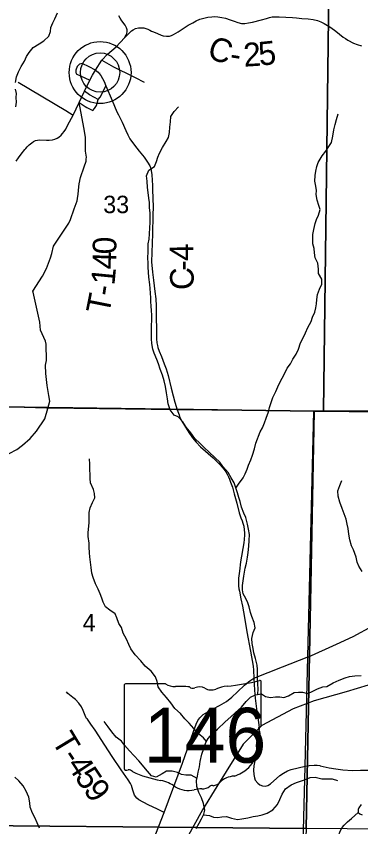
# Model space of a CAD drawing. Extents: x 0 to 191, y 0 to 55.
# Drawn here: x 144.645 to 145.059, y 20.34 to 21.314 of the extents above; entities that cross this region are included whole.
import ezdxf

# ---------------------------------------------------------------- set-up
doc = ezdxf.new("R2010")
doc.units = 0
for name, color, linetype in [('GM_X_Corporation', 7, 'Continuous'), ('GM_X_County_Road', 7, 'Continuous'), ('GM_X_County_Road_Text', 7, 'Continuous'), ('GM_X_Minor_River', 7, 'Continuous'), ('GM_X_Rail_Line', 7, 'Continuous'), ('GM_X_Section_Text', 7, 'Continuous'), ('GM_X_State_Location', 7, 'Continuous'), ('GM_X_State_Route', 7, 'Continuous'), ('GM_X_State_Shield', 7, 'Continuous'), ('GM_X_Township_Road', 7, 'Continuous'), ('GM_X_Township_Road_Text', 7, 'Continuous'), ('GM_X_Unincorporated', 7, 'Continuous'), ('GM_X_Unincorporated_Location', 7, 'Continuous')]:
    doc.layers.add(name, color=color, linetype=linetype)

msp = doc.modelspace()

# ---------------------------------------------------------------- linework, layer by layer
at = {"layer": 'GM_X_Corporation'}
for points in [[(145.17243, 20.8379), (145.0026, 20.83935), (144.83879, 20.8412), (144.83813, 20.84121), (144.68247, 20.843), (144.68103, 20.84301), (144.48078, 20.84928), (144.48001, 20.8493), (144.38601, 20.85042), (144.38393, 20.85044), (143.76753, 20.85776), (143.76581, 20.85778), (143.59684, 20.85979), (143.59377, 20.85978), (143.43969, 20.86008), (143.44633, 20.9725), (143.44634, 20.97335), (143.45423, 21.44428), (143.46697, 22.05758), (143.46706, 22.06228), (143.47318, 22.50936)], [(144.98772, 20.24394), (144.99193, 20.41256), (144.99195, 20.41315), (144.99523, 20.54421), (144.99523, 20.54446), (145.0026, 20.83935), (144.83879, 20.8412), (144.83813, 20.84121), (144.68247, 20.843), (144.68103, 20.84301), (144.48078, 20.84928), (144.48001, 20.8493), (144.38601, 20.85042), (144.38393, 20.85044), (143.76753, 20.85776), (143.76581, 20.85778), (143.59684, 20.85979), (143.59377, 20.85978), (143.43969, 20.86008), (143.27549, 20.86338), (143.27549, 18.61761)], [(144.98772, 20.24394), (144.99193, 20.41256), (144.99195, 20.41315), (144.99523, 20.54421), (144.99523, 20.54446), (145.0026, 20.83935), (145.17243, 20.8379)]]:
    msp.add_lwpolyline(points, dxfattribs=at)
for points in [[(144.51719, 21.34898), (145.0205, 21.34372), (145.01412, 20.83983), (145.00275, 20.8397), (144.50909, 20.84639)], [(145.51832, 21.3384), (145.5104, 20.8362), (145.49144, 20.83655), (145.01412, 20.83983), (145.0205, 21.34372)], [(144.46967, 20.84688), (144.50909, 20.84639), (145.00275, 20.8397), (144.99311, 20.33823), (144.46404, 20.34281)], [(145.00275, 20.8397), (145.01412, 20.83983), (145.49144, 20.83655), (145.48618, 20.33399), (144.99311, 20.33823)], [(144.99311, 20.33823), (144.97358, 19.84025), (144.45738, 19.84668), (144.46404, 20.34281)]]:
    msp.add_lwpolyline(points, close=True, dxfattribs=at)
at = {"layer": 'GM_X_County_Road'}
for points in [[(144.77467, 21.28794), (144.78151, 21.29498), (144.78314, 21.29631), (144.78544, 21.29775), (144.78821, 21.29905), (144.79148, 21.29994), (144.79433, 21.30016), (144.79813, 21.29985), (144.80067, 21.29919), (144.80275, 21.29833), (144.80513, 21.29728), (144.80738, 21.29617), (144.80973, 21.29512), (144.81433, 21.29312), (144.81901, 21.29102), (144.82136, 21.29024), (144.82518, 21.28983), (144.82915, 21.29008), (144.83133, 21.29058), (144.83377, 21.29185), (144.8392, 21.29526), (144.84646, 21.29994), (144.85158, 21.30323), (144.8569, 21.30614), (144.86119, 21.30855), (144.86557, 21.31021), (144.87019, 21.31162), (144.87512, 21.31273), (144.8798, 21.31326), (144.88318, 21.31342), (144.8872, 21.31315), (144.89204, 21.31248), (144.89639, 21.31151), (144.90174, 21.30977), (144.90667, 21.30797), (144.91132, 21.30642), (144.91545, 21.30531), (144.91952, 21.30525), (144.92387, 21.30584), (144.92896, 21.30689), (144.93979, 21.30946), (144.94544, 21.31126), (144.9491, 21.31234), (144.95228, 21.31312), (144.95516, 21.31331), (144.96095, 21.31301), (144.97701, 21.3124), (144.98172, 21.31187), (144.98812, 21.31126), (144.99579, 21.31077), (145.00158, 21.31007), (145.00693, 21.30866), (145.01094, 21.30717), (145.01476, 21.3052), (145.02285, 21.30041), (145.02911, 21.29603), (145.03786, 21.28897), (145.04049, 21.287), (145.04337, 21.28506), (145.05035, 21.28152), (145.05456, 21.27986), (145.05991, 21.2785)], [(144.73977, 21.24925), (144.74297, 21.24687), (144.74453, 21.24513), (144.74635, 21.24271), (144.74843, 21.23915), (144.75025, 21.23559), (144.75243, 21.23033), (144.75988, 21.21252), (144.76569, 21.19908), (144.76768, 21.19535), (144.77189, 21.18663), (144.77627, 21.17649), (144.77874, 21.17133), (144.78126, 21.16664), (144.78681, 21.1591), (144.79262, 21.15177), (144.7983, 21.14448), (144.80264, 21.13859), (144.80533, 21.13416), (144.80663, 21.13095), (144.8071, 21.12844), (144.80771, 21.12323), (144.8084, 21.11075), (144.80862, 21.10533), (144.80918, 21.08494), (144.8091, 21.07493), (144.8085, 21.05261), (144.80723, 21.0189), (144.80832, 21.00637), (144.80953, 20.99696), (144.8114, 20.98321), (144.81239, 20.97436), (144.81287, 20.96621), (144.81291, 20.95814), (144.81296, 20.95069), (144.81313, 20.93924), (144.81322, 20.92631), (144.81369, 20.92163), (144.81452, 20.91834), (144.81504, 20.91595), (144.81651, 20.91148), (144.8192, 20.90511), (144.82267, 20.89648), (144.82488, 20.89032), (144.8274, 20.8823), (144.83099, 20.86721), (144.83317, 20.8581), (144.8352, 20.85034), (144.83823, 20.84094), (144.84045, 20.83492)], [(144.84045, 20.83492), (144.84113, 20.83307), (144.84149, 20.83208), (144.8437, 20.82749), (144.84808, 20.8202), (144.85212, 20.81391), (144.85676, 20.80728), (144.86101, 20.80207), (144.86621, 20.79678), (144.8813, 20.78325), (144.88954, 20.77549), (144.89245, 20.77211), (144.8944, 20.76968), (144.89657, 20.7666), (144.89826, 20.76387), (144.89995, 20.76079), (144.90121, 20.75793), (144.90251, 20.75437), (144.90454, 20.74804), (144.9068, 20.74011), (144.90975, 20.72905), (144.91291, 20.71725), (144.91487, 20.7114), (144.91634, 20.70758), (144.91721, 20.70489), (144.9182, 20.70121), (144.9189, 20.69683), (144.91911, 20.69349), (144.91911, 20.69106), (144.91868, 20.68529), (144.91825, 20.68143), (144.91452, 20.65845), (144.91296, 20.64739), (144.912, 20.63894), (144.91183, 20.63408), (144.91205, 20.62953), (144.91248, 20.62597), (144.91296, 20.62328), (144.91478, 20.61413), (144.91664, 20.60515), (144.91898, 20.59167), (144.92193, 20.57441), (144.92627, 20.55116), (144.92948, 20.53313), (144.92996, 20.52822), (144.93021, 20.51878)], [(144.93021, 20.51878), (144.93128, 20.50436), (144.93209, 20.49471), (144.93339, 20.482), (144.93587, 20.46546), (144.93659, 20.45931), (144.93654, 20.45445), (144.93602, 20.45001), (144.9354, 20.44257), (144.93447, 20.43435), (144.93235, 20.42329), (144.93054, 20.41358), (144.93003, 20.4082), (144.93018, 20.40319), (144.93101, 20.39901), (144.93209, 20.39606), (144.93509, 20.3927), (144.93773, 20.39069), (144.94078, 20.38945), (144.94439, 20.38903), (144.94724, 20.38996), (144.95034, 20.39177), (144.96156, 20.40191), (144.96596, 20.40474), (144.9707, 20.40743), (144.9754, 20.40903), (144.99205, 20.41288), (144.99685, 20.41379), (145.00294, 20.41415), (145.00672, 20.41425), (145.00984, 20.41371)], [(145.00984, 20.41371), (145.01028, 20.41363), (145.02113, 20.41125), (145.02904, 20.4097), (145.03757, 20.40846), (145.04888, 20.408), (145.05875, 20.40826), (145.07162, 20.40826)], [(145.05927, 20.36707), (145.05674, 20.36319), (145.05591, 20.36102), (145.05565, 20.35911), (145.05581, 20.35735), (145.05793, 20.3556), (145.06082, 20.35456)]]:
    msp.add_lwpolyline(points, dxfattribs=at)
at = {"layer": 'GM_X_Minor_River'}
for points in [[(144.64376, 21.23443), (144.64501, 21.24108), (144.64741, 21.24699), (144.65057, 21.25347), (144.65448, 21.25995), (144.65707, 21.26548), (144.66005, 21.27025), (144.66491, 21.27656), (144.67225, 21.28062), (144.6779, 21.28428), (144.68389, 21.29003), (144.68592, 21.29555), (144.68644, 21.30048), (144.68847, 21.30581), (144.69088, 21.31096), (144.6944, 21.3182)], [(144.64424, 21.20505), (144.64476, 21.21055), (144.6447, 21.21624), (144.64484, 21.22117), (144.64384, 21.22647)], [(144.80425, 21.12914), (144.81102, 21.13357), (144.81342, 21.13928), (144.81507, 21.14461), (144.81711, 21.14956), (144.82064, 21.15604), (144.82511, 21.16329), (144.82771, 21.16844), (144.82897, 21.17433), (144.82928, 21.18078), (144.82998, 21.18724), (144.83067, 21.19331), (144.83458, 21.19942), (144.83983, 21.20497)], [(144.90886, 20.7472), (144.91187, 20.75172), (144.91747, 20.75956), (144.92007, 20.76432), (144.92228, 20.76985), (144.92413, 20.7748), (144.92671, 20.78089), (144.92874, 20.78679), (144.93131, 20.7944), (144.93295, 20.80087), (144.93811, 20.81458), (144.94071, 20.81935), (144.94311, 20.82563), (144.94532, 20.83096), (144.9479, 20.83857), (144.94917, 20.84371), (144.95119, 20.84999), (144.9534, 20.85589), (144.95674, 20.86294), (144.95933, 20.86866), (144.96174, 20.87399), (144.96452, 20.87914), (144.96768, 20.88505), (144.97046, 20.89134), (144.97438, 20.89631), (144.97735, 20.90203), (144.98146, 20.90795), (144.98405, 20.91385), (144.98662, 20.92146), (144.98922, 20.92661), (144.99256, 20.93347), (144.99533, 20.94014), (144.99923, 20.94719), (145.00107, 20.95233), (145.00385, 20.95862), (145.00512, 20.96356), (145.00564, 20.9685), (145.00616, 20.97362), (145.00704, 20.97951), (145.00944, 20.98617), (145.01203, 20.99189), (145.01234, 20.99815), (145.0083, 21.00493), (145.00824, 21.01005), (145.00741, 21.01744), (145.00394, 21.02385), (145.00331, 21.02954), (145.00307, 21.03503), (145.00149, 21.0407), (145.00125, 21.0462), (145.00138, 21.05189), (145.00246, 21.05778), (145.00409, 21.06481), (145.00555, 21.06957), (145.00796, 21.07509), (145.00998, 21.08156), (145.0086, 21.08667), (145.00664, 21.09309), (145.00543, 21.09972), (145.00558, 21.10446), (145.00476, 21.10995), (145.00357, 21.11582), (145.00407, 21.12246), (145.00477, 21.12796), (145.00604, 21.13348), (145.00788, 21.13824), (145.01272, 21.14625), (145.01702, 21.15179), (145.02075, 21.15733), (145.02392, 21.16229), (145.02555, 21.1697), (145.02641, 21.1773), (145.02824, 21.18376), (145.02969, 21.19003), (145.0319, 21.1965)], [(144.93525, 20.49933), (144.93578, 20.50652), (144.93535, 20.51126), (144.9349, 20.5179), (144.93479, 20.52909), (144.93435, 20.53458), (144.93219, 20.54234), (144.93042, 20.54934), (144.92942, 20.55426), (144.92841, 20.56032), (144.92778, 20.56639), (144.92941, 20.57361), (144.93181, 20.57914), (144.93061, 20.58557), (144.92789, 20.59275), (144.92651, 20.59767), (144.92493, 20.60448), (144.92317, 20.6094), (144.92066, 20.6143), (144.91757, 20.62015), (144.91676, 20.62507), (144.91671, 20.63019), (144.91741, 20.63551), (144.9183, 20.64121), (144.9192, 20.64596), (144.92009, 20.6509), (144.92155, 20.65699), (144.92261, 20.66402), (144.9235, 20.66953), (144.92437, 20.67731), (144.92487, 20.68396), (144.92498, 20.69117), (144.92397, 20.6976), (144.92277, 20.70385), (144.9208, 20.71161), (144.91828, 20.71689), (144.91556, 20.72426), (144.91378, 20.73088), (144.91222, 20.73598), (144.91084, 20.74147), (144.90674, 20.75338), (144.90327, 20.7596), (144.8996, 20.76582), (144.89328, 20.77296), (144.88945, 20.77804), (144.88371, 20.78348), (144.87606, 20.79061), (144.87109, 20.7953), (144.86574, 20.80075), (144.85943, 20.80675), (144.85444, 20.81334), (144.84907, 20.82011), (144.84483, 20.82652), (144.83928, 20.83272), (144.83453, 20.83456), (144.82973, 20.84115), (144.82738, 20.84815), (144.82637, 20.8542), (144.82554, 20.86159), (144.82433, 20.86917), (144.82237, 20.87578), (144.8204, 20.88278), (144.81787, 20.88977), (144.81572, 20.89639), (144.81377, 20.90168), (144.81067, 20.90904), (144.8091, 20.91414), (144.80771, 20.92096), (144.80727, 20.92626), (144.80721, 20.93195), (144.80735, 20.93726), (144.80748, 20.94276), (144.80761, 20.94845), (144.80754, 20.95528), (144.80749, 20.96021), (144.80706, 20.96589), (144.80663, 20.97082), (144.80639, 20.97575), (144.8059, 20.98674), (144.80547, 20.99186), (144.80424, 21.00057), (144.80361, 21.00644), (144.80336, 21.01232), (144.80331, 21.01725), (144.80306, 21.02388), (144.80336, 21.0309), (144.80312, 21.03583), (144.80326, 21.04057), (144.80434, 21.04608), (144.80503, 21.05254), (144.80534, 21.05974), (144.80565, 21.0662), (144.80554, 21.07738), (144.80509, 21.08401), (144.80484, 21.09008), (144.80403, 21.09538), (144.80339, 21.10201), (144.80257, 21.10807), (144.80193, 21.11565), (144.80129, 21.12228), (144.80425, 21.12914)], [(144.87342, 20.44265), (144.86974, 20.44703), (144.86364, 20.45171), (144.85827, 20.4583), (144.85252, 20.46488), (144.84755, 20.46995), (144.84218, 20.47635), (144.83549, 20.48216), (144.8305, 20.48912), (144.82532, 20.49552), (144.81957, 20.50191), (144.81515, 20.50832), (144.81395, 20.51494), (144.81219, 20.52024), (144.80682, 20.52701), (144.79975, 20.53301), (144.79438, 20.53959), (144.78768, 20.54692), (144.7825, 20.55388), (144.77998, 20.55917), (144.77708, 20.56559), (144.77322, 20.57276), (144.77125, 20.57957), (144.76798, 20.58447), (144.76545, 20.59127), (144.76351, 20.59618), (144.75703, 20.60047), (144.75188, 20.6044), (144.74917, 20.61007), (144.74741, 20.61498), (144.74566, 20.6199), (144.74314, 20.62575), (144.74004, 20.63217), (144.73713, 20.63953), (144.73575, 20.64483), (144.73492, 20.65184), (144.73391, 20.65809), (144.73309, 20.66434), (144.73265, 20.66946), (144.73221, 20.67628), (144.73216, 20.68102), (144.73113, 20.68879), (144.73127, 20.69391), (144.73229, 20.7053), (144.7324, 20.71232), (144.73254, 20.71782), (144.73343, 20.72333), (144.73639, 20.72962), (144.73898, 20.73534), (144.73893, 20.74065), (144.73755, 20.74556), (144.73407, 20.7533), (144.73364, 20.75842), (144.73339, 20.76354), (144.73315, 20.76923), (144.73327, 20.77587), (144.73282, 20.78212)], [(145.06062, 20.64704), (145.05658, 20.65326), (145.05445, 20.65817), (145.05325, 20.66403), (145.05032, 20.67273), (145.048, 20.67763), (145.04565, 20.68482), (145.04463, 20.69183), (145.04362, 20.69845), (145.04262, 20.70394), (145.04142, 20.70962), (145.03889, 20.71623), (145.03675, 20.72247), (145.03383, 20.73022), (145.03167, 20.7374), (145.03142, 20.74385), (145.03381, 20.75032), (145.03602, 20.75622)], [(145.0183, 20.50889), (145.02583, 20.51333), (145.03318, 20.51644), (145.04016, 20.51917), (145.04544, 20.52093), (145.05187, 20.52157), (145.05925, 20.52183)], [(144.86083, 20.33804), (144.86474, 20.34453), (144.86753, 20.34987), (144.87012, 20.3554), (144.87158, 20.36035), (144.8698, 20.36811), (144.86727, 20.37511), (144.86436, 20.38134), (144.86164, 20.38852), (144.86156, 20.39592), (144.86264, 20.40105), (144.86354, 20.4058), (144.86499, 20.41227), (144.86587, 20.41873), (144.86786, 20.42766), (144.87025, 20.43433), (144.87283, 20.44156), (144.87543, 20.44633), (144.88086, 20.45227), (144.88687, 20.45746), (144.89605, 20.46628), (144.90262, 20.47222), (144.90806, 20.47721), (144.91556, 20.48374), (144.92098, 20.49063), (144.92623, 20.49599), (144.93226, 20.4989), (144.93944, 20.49992), (144.94421, 20.49675), (144.95047, 20.49548), (144.95652, 20.49649), (144.96163, 20.49617), (144.96656, 20.49546), (144.97222, 20.49741), (144.979, 20.50147), (144.98391, 20.50209), (144.98884, 20.50195), (144.99491, 20.5003), (144.99982, 20.50225), (145.00678, 20.50593), (145.0132, 20.50827), (145.0183, 20.50889)], [(144.86209, 20.39843), (144.85487, 20.40211), (144.84843, 20.40223), (144.8435, 20.40294), (144.83874, 20.40536), (144.83229, 20.407), (144.82528, 20.40692), (144.82002, 20.40384), (144.81286, 20.39997), (144.80735, 20.40162), (144.80237, 20.40707), (144.79202, 20.41948), (144.78609, 20.42568), (144.78073, 20.43132), (144.77498, 20.43809), (144.77114, 20.44298), (144.76484, 20.44804), (144.75967, 20.45425), (144.75525, 20.46046), (144.75026, 20.46667)], [(144.67244, 20.33838), (144.66992, 20.3448), (144.66701, 20.35122), (144.6643, 20.35651), (144.66158, 20.36388), (144.66115, 20.369), (144.65994, 20.37581), (144.65646, 20.38299), (144.65279, 20.3894), (144.64762, 20.39561), (144.64284, 20.39992)], [(144.86983, 20.35478), (144.87695, 20.35377), (144.88189, 20.35192), (144.88682, 20.3514), (144.89193, 20.35221), (144.89741, 20.35246), (144.90368, 20.35063), (144.91089, 20.34918), (144.91581, 20.3498), (144.92299, 20.35101), (144.92941, 20.35279), (144.93527, 20.35323), (144.94037, 20.35442), (144.9466, 20.35657), (144.95337, 20.36062), (144.9588, 20.36713), (144.96177, 20.37285), (144.96454, 20.37933), (144.96845, 20.38563), (144.97522, 20.39045), (144.98162, 20.39336), (144.99125, 20.39668), (144.99822, 20.39941), (145.00409, 20.39966), (145.01206, 20.39784), (145.01888, 20.39772), (145.02456, 20.39778), (145.03101, 20.39595)]]:
    msp.add_lwpolyline(points, dxfattribs=at)
at = {"layer": 'GM_X_Rail_Line'}
msp.add_lwpolyline([(145.06789, 20.5105), (145.04149, 20.5022), (145.00279, 20.49157), (144.97779, 20.48186), (144.94013, 20.46187), (144.91759, 20.43929), (144.88602, 20.38854), (144.86877, 20.36042), (144.84152, 20.31115)], dxfattribs=at)
at = {"layer": 'GM_X_State_Route'}
for points in [[(144.64445, 21.13985), (144.64738, 21.14375), (144.65076, 21.14821), (144.65508, 21.15389), (144.65608, 21.15505), (144.65788, 21.15721), (144.66034, 21.15962), (144.66336, 21.16203), (144.66544, 21.16336), (144.66766, 21.1645), (144.67026, 21.16511), (144.67278, 21.16541), (144.68084, 21.16516), (144.68441, 21.16516), (144.68826, 21.16544), (144.69087, 21.16605), (144.6938, 21.16743), (144.69602, 21.16873), (144.69851, 21.17092), (144.70042, 21.17294), (144.70239, 21.17557), (144.70413, 21.17823), (144.7064, 21.18247), (144.71106, 21.19142), (144.71294, 21.19524), (144.7202, 21.21049), (144.72673, 21.22379), (144.73334, 21.23709), (144.73642, 21.24316), (144.73977, 21.24925), (144.7475, 21.261), (144.75459, 21.26831), (144.7647, 21.27736), (144.77467, 21.28794), (144.7768, 21.29141), (144.77746, 21.29315), (144.77788, 21.29539), (144.77788, 21.29742), (144.77719, 21.30013), (144.77561, 21.30329), (144.77174, 21.30855), (144.76962, 21.31151), (144.76801, 21.31447)], [(144.99441, 20.54384), (144.99534, 20.54419), (145.02977, 20.55952), (145.0498, 20.569), (145.07364, 20.58154)], [(144.80975, 20.32456), (144.8226, 20.35729), (144.84471, 20.41653), (144.85067, 20.43377), (144.85825, 20.45589), (144.86096, 20.46365), (144.86313, 20.4678), (144.86548, 20.47114), (144.86773, 20.47349), (144.86963, 20.47512), (144.87234, 20.47674), (144.88163, 20.4818), (144.88922, 20.48595), (144.89743, 20.49064), (144.90402, 20.49597), (144.91079, 20.50238), (144.91901, 20.51032), (144.92379, 20.51438), (144.92677, 20.51646), (144.93021, 20.51878), (144.96484, 20.53244), (144.99441, 20.54384)]]:
    msp.add_lwpolyline(points, dxfattribs=at)
at = {"layer": 'GM_X_State_Shield'}
for p, q in [((144.77446, 20.51022), (144.77446, 20.41016)), ((144.82434, 20.51195), (144.77608, 20.51195)), ((144.93925, 20.46208), (144.93925, 20.51443)), ((144.93923, 20.4621), (144.93925, 20.46208))]:
    msp.add_line(p, q, dxfattribs=at)
for centre, major_axis, start_param, end_param in [((144.77635, 20.51044), (0.00191, 0), 1.712693, 3.28349), ((144.83583, 20.52356), (0.01852, 0), 4.042523, 4.731795), ((144.84197, 20.45577), (0.06648, 0), 1.404758, 1.657858), ((144.85707, 20.51096), (0.00534, 0), 3.836095, 5.185415), ((144.86491, 20.49939), (0.01111, 0), 0.950623, 2.079405), ((144.87924, 20.51525), (0.01336, 0), 4.081561, 5.145723), ((144.90284, 20.48138), (0.03516, 0), 1.699011, 2.107814), ((144.88055, 20.64836), (0.17476, 0), 4.814394, 5.042369), ((144.93742, 20.51464), (0.00183, 0), 6.141152, 7.989035), ((144.93883, 20.45824), (0.00284, 0), 1.883978, 3.671073), ((144.93729, 20.46188), (0.00196, 0), 5.05454, 6.418171), ((144.92077, 20.45162), (0.01704, 0), 5.934695, 6.695948), ((144.89034, 20.43352), (0.04371, 0), 5.101752, 6.440018), ((144.94582, 20.44018), (0.0124, 0), 2.387724, 3.262537), ((144.77636, 20.40995), (0.00193, 0), 3.00124, 4.508301), ((144.77666, 20.42018), (0.0147, 0), 4.665946, 4.897461), ((144.77966, 20.40439), (0.0053, 0), 0.519207, 1.627899), ((144.84658, 20.49429), (0.1262, 0), 4.195997, 4.488961), ((144.90877, 20.38207), (0.02394, 0), 1.647645, 2.488434), ((144.80895, 20.36521), (0.03949, 0), 0.823519, 1.323587), ((144.88004, 20.38671), (0.00376, 0), 1.147584, 2.315152), ((144.87844, 20.40047), (0.01412, 0), 4.937069, 5.64225), ((144.85166, 20.40389), (0.02506, 0), 4.026481, 4.996735), ((144.86613, 20.3693), (0.02059, 0), 1.495662, 1.94098), ((144.86796, 20.3964), (0.01335, 0), 4.691044, 5.507374)]:
    msp.add_ellipse(centre, major_axis=major_axis, ratio=0.8, start_param=start_param, end_param=end_param, dxfattribs=at)
at = {"layer": 'GM_X_Township_Road'}
for p, q in [((144.64687, 21.23486), (144.70413, 21.20052)), ((144.70413, 21.20052), (144.71294, 21.19524))]:
    msp.add_line(p, q, dxfattribs=at)
for points in [[(144.73977, 21.24925), (144.73247, 21.2532), (144.72385, 21.25731), (144.72085, 21.2565), (144.71808, 21.25337), (144.71651, 21.24904), (144.71625, 21.24687), (144.71677, 21.24479), (144.73334, 21.23709)], [(144.7475, 21.261), (144.76144, 21.25329), (144.77055, 21.24878), (144.77653, 21.24591), (144.78772, 21.24045), (144.79839, 21.23481)], [(144.7202, 21.21049), (144.72736, 21.20567), (144.72935, 21.20437), (144.73672, 21.20055), (144.73889, 21.20307), (144.74097, 21.20671), (144.74323, 21.21408), (144.74548, 21.21686), (144.74739, 21.22033), (144.75243, 21.23033)], [(144.74323, 21.21408), (144.73872, 21.21625), (144.73282, 21.21946), (144.72673, 21.22379)], [(144.72777, 21.16038), (144.72782, 21.16878), (144.72574, 21.18041), (144.7202, 21.21049)], [(144.72112, 21.11612), (144.7212, 21.1166), (144.72191, 21.12025), (144.72645, 21.13318), (144.7286, 21.13968), (144.7289, 21.14207), (144.72902, 21.14481), (144.72813, 21.15198), (144.72774, 21.15565), (144.72777, 21.16038)], [(144.66511, 20.98231), (144.66479, 20.98379), (144.67642, 21.00168), (144.68107, 21.01092), (144.6859, 21.02357), (144.68763, 21.02893), (144.68948, 21.0377), (144.70791, 21.06531), (144.71005, 21.0699), (144.71423, 21.08273), (144.71786, 21.09233), (144.7184, 21.09513), (144.71912, 21.10002), (144.71989, 21.10891), (144.72049, 21.11278), (144.72112, 21.11612)], [(144.68387, 20.85828), (144.68172, 20.87018), (144.68016, 20.88474), (144.67994, 20.89463), (144.68031, 20.89692), (144.68089, 20.90047), (144.68071, 20.92003), (144.6797, 20.92361), (144.67385, 20.93685), (144.67284, 20.94628), (144.66511, 20.98231)], [(144.63634, 20.78859), (144.64517, 20.79354), (144.65232, 20.79855), (144.66139, 20.80649), (144.66896, 20.81537), (144.67892, 20.8304), (144.68258, 20.84273), (144.68512, 20.85133), (144.68387, 20.85828)], [(144.8226, 20.35729), (144.81447, 20.36129), (144.80337, 20.3667), (144.79209, 20.37257), (144.78947, 20.37465), (144.78703, 20.37808), (144.78592, 20.38068), (144.78469, 20.38422), (144.78306, 20.38978), (144.78198, 20.39243), (144.77927, 20.39658), (144.77078, 20.40859), (144.76013, 20.42457), (144.75114, 20.43818), (144.73949, 20.45622), (144.73451, 20.46359), (144.73023, 20.46949), (144.72908, 20.47049), (144.72815, 20.47199), (144.72522, 20.47986), (144.72298, 20.48418), (144.71982, 20.48885), (144.71577, 20.49328), (144.7128, 20.49571), (144.70683, 20.5003), (144.70498, 20.50215)], [(144.99726, 20.257), (145.00072, 20.26232), (145.01219, 20.28237), (145.01504, 20.28682), (145.0202, 20.2939), (145.02222, 20.29684), (145.02377, 20.29911), (145.02516, 20.30191), (145.0262, 20.30413), (145.02723, 20.30743), (145.02806, 20.31048), (145.02894, 20.31467), (145.031, 20.32562), (145.0325, 20.33074), (145.03364, 20.33379), (145.03503, 20.33648), (145.03679, 20.33932), (145.03896, 20.34206), (145.04041, 20.34397), (145.04299, 20.34624), (145.04764, 20.35017), (145.05581, 20.35735)]]:
    msp.add_lwpolyline(points, dxfattribs=at)
at = {"layer": 'GM_X_Unincorporated'}
for radius in [0.0372, 0.02358]:
    msp.add_circle((144.74551, 21.24627), radius, dxfattribs=at)
at = {"layer": 'GM_X_Unincorporated_Location'}
msp.add_line((144.74551, 21.24627), (144.74551, 21.24627), dxfattribs=at)

# ---------------------------------------------------------------- texts
at = {"layer": 'GM_X_County_Road_Text'}
for s, rotation, p in [('C', 340.48506, (144.8728, 21.26453)), ('2', 3.64803, (144.91866, 21.25324)), ('5', 5.82964, (144.9373, 21.25445)), ('-', 351.23904, (144.90043, 21.25532)), ('4', 90.49474, (144.85777, 21.01994)), ('-', 90.47792, (144.85787, 21.00837)), ('C', 91.20554, (144.85836, 20.98531))]:
    msp.add_text(s, height=0.02841, rotation=rotation, dxfattribs=at).set_placement(p)
at = {"layer": 'GM_X_Section_Text'}
for s, height, p in [('33', 0.020928, (144.74928, 21.07737)), ('4', 0.02093, (144.72449, 20.57503))]:
    msp.add_text(s, height=height, rotation=0.00001, dxfattribs=at).set_placement(p)
at = {"layer": 'GM_X_State_Location'}
for s in ['s', 'r']:
    msp.add_text(s, height=0.0000947, dxfattribs=at).set_placement((144.855, 20.45354))
msp.add_text('146', height=0.0000947, rotation=0.00001, dxfattribs=at).set_placement((144.82157, 20.44665))
at = {"layer": 'GM_X_State_Shield'}
msp.add_text('146', height=0.065918, dxfattribs=at).set_placement((144.79817, 20.41722))
at = {"layer": 'GM_X_Township_Road_Text'}
for s, rotation, p in [('0', 90, (144.76505, 21.02801)), ('4', 88.15281, (144.76447, 21.00952)), ('1', 84.45843, (144.76265, 20.99011)), ('-', 80.76405, (144.76052, 20.97661)), ('T', 78.91686, (144.75626, 20.95477)), ('T', 301.24673, (144.68652, 20.4435)), ('-', 303.34333, (144.69815, 20.42437)), ('4', 303.3694, (144.70457, 20.41462)), ('5', 303.52091, (144.71424, 20.39993)), ('9', 305.45039, (144.72449, 20.38448))]:
    msp.add_text(s, height=0.02841, rotation=rotation, dxfattribs=at).set_placement(p)

doc.saveas('drawing.dxf')
